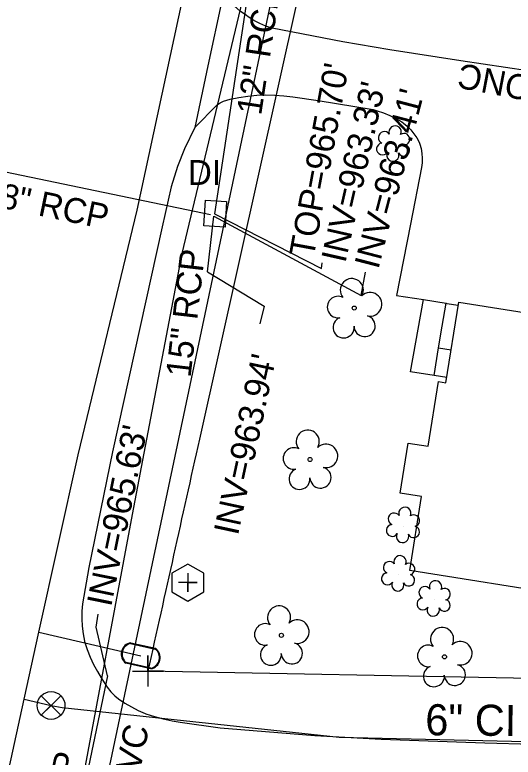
# Model space of a CAD drawing. Extents: x 1614611 to 1617571, y 898867 to 905462.
# Drawn here: x 1616334.4 to 1616414.5, y 900246.3 to 900365.7 of the extents above; entities that cross this region are included whole.
import ezdxf

# ---------------------------------------------------------------- set-up
doc = ezdxf.new("R2010")
doc.units = 0
for name, color, linetype in [('Exist Building', 7, 'Continuous'), ('Exist Other Culture Area Outline', 7, 'Continuous'), ('Exist Roads EOP Other Text', 7, 'Continuous'), ('Exist Structure Minor Catch Basin Top Elevation', 7, 'Continuous'), ('Exist Structure Minor Pipes RCP 12 Inch Invert', 7, 'Continuous'), ('Exist Structure Minor Pipes RCP 15 Inch Invert', 7, 'Continuous'), ('Exist Utilities Sanitary Sewer UG Line', 7, 'Continuous'), ('Exist Utilities Sanitary Sewer UG Line Text', 7, 'Continuous'), ('Exist Utilities Telephone UG FO SUE LOS B', 7, 'Continuous'), ('Exist Utilities Water UG Line SUE LOS B', 7, 'Continuous'), ('Exist Utilities Water UG Line SUE LOS B Text', 7, 'Continuous'), ('Exist Vegetation Shrub CELL', 7, 'Continuous'), ('Exist Vegetation Tree CELL', 7, 'Continuous'), ('Prop Drainage Structure Catch Basin Adjust CELL', 7, 'Continuous'), ('Prop Drainage Structure Drop Inlet Grate 3 Narrow Slots and Sag Grates 840 24 Label', 7, 'Continuous'), ('Prop Drainage Structure Pipe Stub Out CELL', 7, 'Continuous'), ('Prop Drainage Structure Removal Label', 7, 'Continuous'), ('Prop Drainage Structure Tops and Inverts LABEL', 7, 'Continuous'), ('Prop Earthen Structure Cut Ditch Special Back of Curb Detail Label', 7, 'Continuous'), ('Prop Earthen Structure Head Ditch Label', 7, 'Continuous'), ('Prop Earthen Structure V Ditch Detail Label', 7, 'Continuous'), ('Prop Erosion Embankment Toe Protection CELL', 7, 'Continuous'), ('Prop Erosion Embankment Toe Protection with Rip Rap 2 Detail CELL', 7, 'Continuous'), ('Prop Erosion Embankment Toe Protection with Rip Rap 3 Detail CELL', 7, 'Continuous'), ('Prop Plan Preparation Grade to Drain Arrows CELL', 7, 'Continuous'), ('Prop Plan Preparation Grade to Drain Arrows Label', 7, 'Continuous'), ('Prop Plan Preparation Table Ditch Data CELL', 7, 'Continuous'), ('Prop SS Transition Line', 7, 'Continuous'), ('Scratch_Level_1', 7, 'Continuous'), ('Scratch_Level_9', 7, 'Continuous')]:
    doc.layers.add(name, color=color, linetype=linetype)

msp = doc.modelspace()

# ---------------------------------------------------------------- linework, layer by layer
at = {"layer": 'Exist Building'}
msp.add_lwpolyline([(1616400.89, 900296.31), (1616402.54, 900306.71), (1616403.74, 900306.52), (1616405.79, 900319.48), (1616430.18, 900315.61), (1616430.28, 900316.18), (1616441.58, 900314.39), (1616439.47, 900301.09), (1616441.32, 900300.8), (1616439.7, 900290.54), (1616437.84, 900290.84), (1616434.57, 900270.24), (1616423.44, 900272.01), (1616423.48, 900272.26), (1616397.91, 900276.32), (1616399.8, 900288.22), (1616396.36, 900288.77), (1616397.64, 900296.83)], close=True, dxfattribs=at)
at = {"layer": 'Exist Other Culture Area Outline'}
for points in [[(1616401.84, 900307.68), (1616398.04, 900308.29), (1616400.11, 900319.89)], [(1616402.54, 900312.17), (1616403.15, 900315.65), (1616403.76, 900319.32)], [(1616403.87, 900307.36), (1616401.84, 900307.68), (1616402.54, 900312.17), (1616404.58, 900311.85)]]:
    msp.add_lwpolyline(points, dxfattribs=at)
at = {"layer": 'Exist Utilities Sanitary Sewer UG Line'}
msp.add_lwpolyline([(1616305.43, 900049.6), (1616345.82, 900226.73), (1616377.74, 900378.04)], dxfattribs=at)
at = {"layer": 'Exist Utilities Telephone UG FO SUE LOS B'}
msp.add_lwpolyline([(1616264.27, 899888.11), (1616275.63, 899938.03), (1616283.17, 899975.46), (1616294.6, 900026.16), (1616305.05, 900073.25), (1616315.15, 900117.57), (1616325.55, 900164.34), (1616332.62, 900198.17), (1616344.78, 900239.81), (1616353.34, 900285.35), (1616361.31, 900327.32), (1616372.74, 900375.18)], dxfattribs=at)
at = {"layer": 'Exist Utilities Water UG Line SUE LOS B'}
msp.add_line((1616338.25, 900266.44), (1616354.64, 900262.62), dxfattribs=at)
for points in [[(1616263.66, 899921.5), (1616269.73, 899949.09), (1616273.73, 899969.37), (1616281.36, 900005.29), (1616288.43, 900036.76), (1616298.97, 900086.16), (1616304.15, 900111.94), (1616312.34, 900147.74), (1616321.8, 900194.38), (1616329.08, 900224.67), (1616335.91, 900255.64), (1616338.25, 900266.44), (1616344.58, 900294.92), (1616354.08, 900334.27), (1616364.03, 900380.59)], [(1616335.91, 900255.64), (1616340.22, 900254.64), (1616341.98, 900254.3), (1616386.58, 900249.54), (1616425.84, 900248.61), (1616456.25, 900247.99), (1616477.07, 900247.24)]]:
    msp.add_lwpolyline(points, dxfattribs=at)
at = {"layer": 'Exist Vegetation Shrub CELL'}
for p, q in [((1616395.32, 900344.81), (1616395.32, 900344.81)), ((1616396.9, 900283.49), (1616396.9, 900283.49)), ((1616396.12, 900275.7), (1616396.12, 900275.7)), ((1616401.83, 900271.67), (1616401.83, 900271.67))]:
    msp.add_line(p, q, dxfattribs=at)
for centre, radius, start, end in [((1616395.55, 900346.85), 0.99, 334.8391, 200.4717), ((1616393.84, 900345.94), 0.968, 35.8908, 245.4216), ((1616396.99, 900345.68), 0.929, 284.4567, 126.0861), ((1616393.52, 900344.11), 0.955, 95.1099, 327.9534), ((1616396.96, 900343.88), 0.937, 204.9913, 73.4601), ((1616395.19, 900343.13), 0.984, 151.2797, 21.387), ((1616397.12, 900285.53), 0.99, 334.8391, 200.4717), ((1616395.41, 900284.62), 0.968, 35.8908, 245.4216), ((1616398.57, 900284.36), 0.929, 284.4567, 126.0861), ((1616395.1, 900282.79), 0.955, 95.1099, 327.9534), ((1616398.53, 900282.56), 0.937, 204.9913, 73.4601), ((1616396.77, 900281.81), 0.984, 151.2797, 21.387), ((1616396.35, 900277.74), 0.99, 334.8391, 200.4717), ((1616394.64, 900276.83), 0.968, 35.8908, 245.4216), ((1616397.79, 900276.57), 0.929, 284.4567, 126.0861), ((1616394.32, 900275), 0.955, 95.1099, 327.9534), ((1616397.76, 900274.78), 0.937, 204.9913, 73.4601), ((1616395.99, 900274.02), 0.984, 151.2797, 21.387), ((1616402.06, 900273.71), 0.99, 334.8391, 200.4717), ((1616400.35, 900272.79), 0.968, 35.8908, 245.4216), ((1616403.5, 900272.54), 0.929, 284.4567, 126.0861), ((1616400.03, 900270.96), 0.955, 95.1099, 327.9534), ((1616403.47, 900270.74), 0.937, 204.9913, 73.4601), ((1616401.7, 900269.98), 0.984, 151.2797, 21.387)]:
    msp.add_arc(centre, radius, start, end, dxfattribs=at)
at = {"layer": 'Exist Vegetation Tree CELL'}
for p, q in [((1616388.98, 900318.54), (1616388.98, 900318.54)), ((1616381.88, 900294.19), (1616381.88, 900294.19)), ((1616377.27, 900265.92), (1616377.27, 900265.92)), ((1616403.5, 900262.46), (1616403.5, 900262.46))]:
    msp.add_line(p, q, dxfattribs=at)
for centre in [(1616388.98, 900318.54), (1616381.88, 900294.19), (1616377.27, 900265.92), (1616403.5, 900262.46)]:
    msp.add_circle(centre, 0.326, dxfattribs=at)
for centre, radius, start, end in [((1616388.59, 900321.42), 1.86, 330.1651, 219.7134), ((1616386.37, 900318.7), 1.73, 62.6636, 279.3457), ((1616391.53, 900319.13), 1.9, 257.1011, 134.1999), ((1616387.27, 900315.42), 1.69, 111.5671, 6.231), ((1616390.65, 900315.64), 1.7, 181.2822, 74.56), ((1616381.5, 900297.07), 1.86, 330.1651, 219.7134), ((1616384.43, 900294.78), 1.9, 257.1011, 134.1999), ((1616379.28, 900294.35), 1.73, 62.6636, 279.3457), ((1616383.56, 900291.29), 1.7, 181.2822, 74.56), ((1616380.18, 900291.07), 1.69, 111.5671, 6.231), ((1616376.89, 900268.79), 1.86, 330.1651, 219.7134), ((1616379.82, 900266.51), 1.9, 257.1011, 134.1999), ((1616374.67, 900266.07), 1.73, 62.6636, 279.3457), ((1616403.11, 900265.33), 1.86, 330.1651, 219.7134), ((1616375.57, 900262.8), 1.69, 111.5671, 6.231), ((1616378.95, 900263.02), 1.7, 181.2822, 74.56), ((1616400.89, 900262.61), 1.73, 62.6636, 279.3457), ((1616406.04, 900263.05), 1.9, 257.1011, 134.1999), ((1616401.79, 900259.34), 1.69, 111.5671, 6.231), ((1616405.17, 900259.56), 1.7, 181.2822, 74.56)]:
    msp.add_arc(centre, radius, start, end, dxfattribs=at)
at = {"layer": 'Prop Drainage Structure Pipe Stub Out CELL'}
msp.add_line((1616362.22, 900274.4), (1616362.22, 900274.4), dxfattribs=at)
msp.add_lwpolyline([(1616359.64, 900275.9), (1616359.63, 900272.92), (1616362.21, 900271.42), (1616364.79, 900272.91), (1616364.8, 900275.89), (1616362.22, 900277.38)], close=True, dxfattribs=at)
msp.add_lwpolyline([(1616362.22, 900275.92), (1616362.22, 900272.89), (1616362.22, 900274.4), (1616363.73, 900274.4), (1616360.7, 900274.4)], dxfattribs=at)
at = {"layer": 'Prop Drainage Structure Removal Label'}
for points in [[(1616366.41, 900333.33), (1616390.11, 900320.54), (1616390.81, 900324.33)], [(1616365.37, 900324.37), (1616374.51, 900318.83), (1616373.8, 900316.03)], [(1616349.29, 900259.43), (1616347.49, 900267.25), (1616347.8, 900269.32)]]:
    msp.add_lwpolyline(points, dxfattribs=at)
at = {"layer": 'Prop Drainage Structure Tops and Inverts LABEL'}
msp.add_line((1616355.79, 900260.18), (1616355.79, 900260.18), dxfattribs=at)
msp.add_lwpolyline([(1616353.29, 900260.18), (1616358.29, 900260.18), (1616355.79, 900260.18), (1616355.79, 900262.68), (1616355.79, 900257.68)], dxfattribs=at)
at = {"layer": 'Prop Earthen Structure Cut Ditch Special Back of Curb Detail Label'}
msp.add_line((1616372.01, 900370.1), (1616366.5, 900333.68), dxfattribs=at)
at = {"layer": 'Prop Earthen Structure Head Ditch Label'}
for p, q in [((1616422.04, 900557.94), (1616364.07, 900297.45)), ((1616631.19, 900254.82), (1616355.79, 900260.18))]:
    msp.add_line(p, q, dxfattribs=at)
msp.add_arc((1713946.87, 878581.13), 99970, 167.4537079, 167.4755873, dxfattribs=at)
at = {"layer": 'Prop Earthen Structure V Ditch Detail Label'}
msp.add_lwpolyline([(1616341.79, 900256.21), (1616338.64, 900253.06), (1616340.22, 900254.64), (1616341.79, 900253.06), (1616338.64, 900256.21)], dxfattribs=at)
msp.add_circle((1616340.22, 900254.64), 2.23, dxfattribs=at)
at = {"layer": 'Prop Erosion Embankment Toe Protection CELL'}
msp.add_lwpolyline([(1616365.06, 900335.9), (1616368.46, 900335.68), (1616368.2, 900331.56), (1616364.8, 900331.78)], close=True, dxfattribs=at)
at = {"layer": 'Prop Erosion Embankment Toe Protection with Rip Rap 3 Detail CELL'}
msp.add_line((1616311.43, 900344.89), (1616365.86, 900333.61), dxfattribs=at)
at = {"layer": 'Prop Plan Preparation Grade to Drain Arrows Label'}
msp.add_lwpolyline([(1616366.5, 900333.68), (1616383.71, 900324.91), (1616383.82, 900325.83)], dxfattribs=at)
at = {"layer": 'Prop Plan Preparation Table Ditch Data CELL'}
for p, q in [((1616365.37, 900324.37), (1616366.41, 900333.33)), ((1616349.29, 900259.43), (1616341.86, 900223.71))]:
    msp.add_line(p, q, dxfattribs=at)
at = {"layer": 'Prop SS Transition Line'}
msp.add_line((1616354.64, 900262.62), (1616354.64, 900262.62), dxfattribs=at)
for points in [[(1616353, 900264.6), (1616356.97, 900263.7)], [(1616353.03, 900264.73), (1616357, 900263.83)], [(1616356.25, 900260.51), (1616352.25, 900261.42)], [(1616356.28, 900260.65), (1616352.28, 900261.56)]]:
    msp.add_lwpolyline(points, dxfattribs=at)
for centre, radius, start, end in [((1616353.36, 900262.91), 1.86, 100.3665, 233.1679), ((1616353.37, 900262.91), 1.73, 102.4894, 230.9709), ((1616355.9, 900262.34), 1.86, 280.8368, 53.4969), ((1616355.91, 900262.34), 1.73, 282.3157, 52.0613)]:
    msp.add_arc(centre, radius, start, end, dxfattribs=at)
at = {"layer": 'Scratch_Level_1'}
for points in [[(1616445.83, 900342.39), (1616436.41, 900343.7), (1616438.13, 900353.64), (1616424.1, 900355.61), (1616406.15, 900358.29), (1616394.68, 900360.06), (1616387.14, 900361.35), (1616375.79, 900363.52), (1616374.78, 900363.87), (1616373.79, 900364.3), (1616372.84, 900364.79), (1616371.93, 900365.36), (1616371.63, 900365.56), (1616370.65, 900366.29), (1616369.72, 900367.08), (1616368.85, 900367.93), (1616368.45, 900368.36), (1616367.76, 900368.28)], [(1616363.35, 900347.56), (1616366.93, 900351.21), (1616367.41, 900351.54), (1616367.93, 900351.8), (1616368.49, 900351.99), (1616369.02, 900352.12), (1616370.44, 900352.41), (1616371.87, 900352.63), (1616373.32, 900352.76), (1616374.77, 900352.81), (1616376.22, 900352.79), (1616377.66, 900352.68), (1616379.1, 900352.5), (1616383.18, 900351.89), (1616392.05, 900350.44), (1616392.67, 900350.27), (1616393.71, 900349.93), (1616394.71, 900349.52), (1616395.69, 900349.03), (1616396.62, 900348.48), (1616396.88, 900348.29), (1616397.5, 900347.78), (1616398.07, 900347.21), (1616398.58, 900346.58), (1616399.03, 900345.91), (1616399.41, 900345.19), (1616399.52, 900344.9), (1616399.73, 900344.17), (1616399.87, 900343.41), (1616399.92, 900342.65), (1616399.9, 900341.88), (1616399.79, 900341.12), (1616398.02, 900332.02), (1616395.78, 900320.56), (1616400.11, 900319.89), (1616403.76, 900319.32), (1616403.9, 900319.3), (1616405.72, 900319.01)]]:
    msp.add_lwpolyline(points, dxfattribs=at)
at = {"layer": 'Scratch_Level_9'}
msp.add_lwpolyline([(1616367.76, 900368.28), (1616365.44, 900357.46), (1616363.35, 900347.56), (1616361.67, 900344.15), (1616360.54, 900341.32), (1616359.56, 900338.03), (1616358.09, 900331.58), (1616350.12, 900295.42), (1616346.3, 900276.84), (1616345.29, 900271), (1616345.19, 900269.79), (1616345.17, 900268.58), (1616345.22, 900267.37), (1616345.36, 900266.16), (1616345.58, 900264.97), (1616345.59, 900264.91), (1616346, 900263.66), (1616346.49, 900262.43), (1616347.05, 900261.24), (1616347.68, 900260.08), (1616348.28, 900259.11), (1616348.73, 900258.31), (1616349.26, 900257.56), (1616349.84, 900256.86), (1616350.49, 900256.21), (1616351.06, 900255.72), (1616352.07, 900255.03), (1616353.13, 900254.41), (1616354.23, 900253.85), (1616355.36, 900253.37), (1616355.48, 900253.32), (1616356.86, 900252.87), (1616358.26, 900252.48), (1616359.69, 900252.17), (1616361, 900251.95), (1616367.39, 900251.06), (1616370.73, 900250.79), (1616382.66, 900249.79), (1616393.29, 900249.2), (1616410, 900248.63), (1616425.32, 900248.21)], dxfattribs=at)

# ---------------------------------------------------------------- texts
at = {"layer": 'Exist Roads EOP Other Text'}
msp.add_text(" 11' CONC", height=4, rotation=169.2367, dxfattribs=at).set_placement((1616431.34, 900353.15))
at = {"layer": 'Exist Structure Minor Catch Basin Top Elevation'}
msp.add_text("TOP=965.70'", height=4, rotation=79.5395, dxfattribs=at).set_placement((1616382.43, 900326.49))
at = {"layer": 'Exist Structure Minor Pipes RCP 12 Inch Invert'}
msp.add_text("INV=963.41'", height=4, rotation=75.3949, dxfattribs=at).set_placement((1616392.84, 900324.64))
at = {"layer": 'Exist Structure Minor Pipes RCP 15 Inch Invert'}
for s, rotation, p in [("INV=963.33'", 77.2097, (1616387.54, 900325.66)), ("INV=963.94'", 77.8418, (1616370.26, 900281.85)), ("INV=965.63'", 78.5101, (1616349.87, 900270.38))]:
    msp.add_text(s, height=4, rotation=rotation, dxfattribs=at).set_placement(p)
at = {"layer": 'Exist Utilities Sanitary Sewer UG Line Text'}
msp.add_text('8" PVC', height=4, rotation=78.0873, dxfattribs=at).set_placement((1616352.44, 900234.12))
at = {"layer": 'Exist Utilities Water UG Line SUE LOS B Text'}
msp.add_text('6" CI', height=5, rotation=359.4815, dxfattribs=at).set_placement((1616400.39, 900249.86))
at = {"layer": 'Prop Drainage Structure Catch Basin Adjust CELL'}
msp.add_text('DI', height=4, dxfattribs=at).set_placement((1616362.21, 900338.34))
at = {"layer": 'Prop Drainage Structure Drop Inlet Grate 3 Narrow Slots and Sag Grates 840 24 Label'}
msp.add_text('18" RCP', height=4, rotation=348.2843, dxfattribs=at).set_placement((1616328.83, 900335.36))
at = {"layer": 'Prop Erosion Embankment Toe Protection with Rip Rap 2 Detail CELL'}
for rotation, p in [(83.3716, (1616362.64, 900307.27)), (78.2456, (1616340.68, 900226.53))]:
    msp.add_text('15" RCP', height=4, rotation=rotation, dxfattribs=at).set_placement(p)
at = {"layer": 'Prop Plan Preparation Grade to Drain Arrows CELL'}
msp.add_text('12" RCP', height=4, rotation=81.3904, dxfattribs=at).set_placement((1616374, 900349.42))

doc.saveas('drawing.dxf')
